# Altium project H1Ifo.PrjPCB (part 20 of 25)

## Sheet IfoEndY1.SchDoc: D1800185
size C; Engineer: Daniel Sigg; DocumentNumber: 5; Revision: 4; SheetNumber: 5; SheetTotal: 8
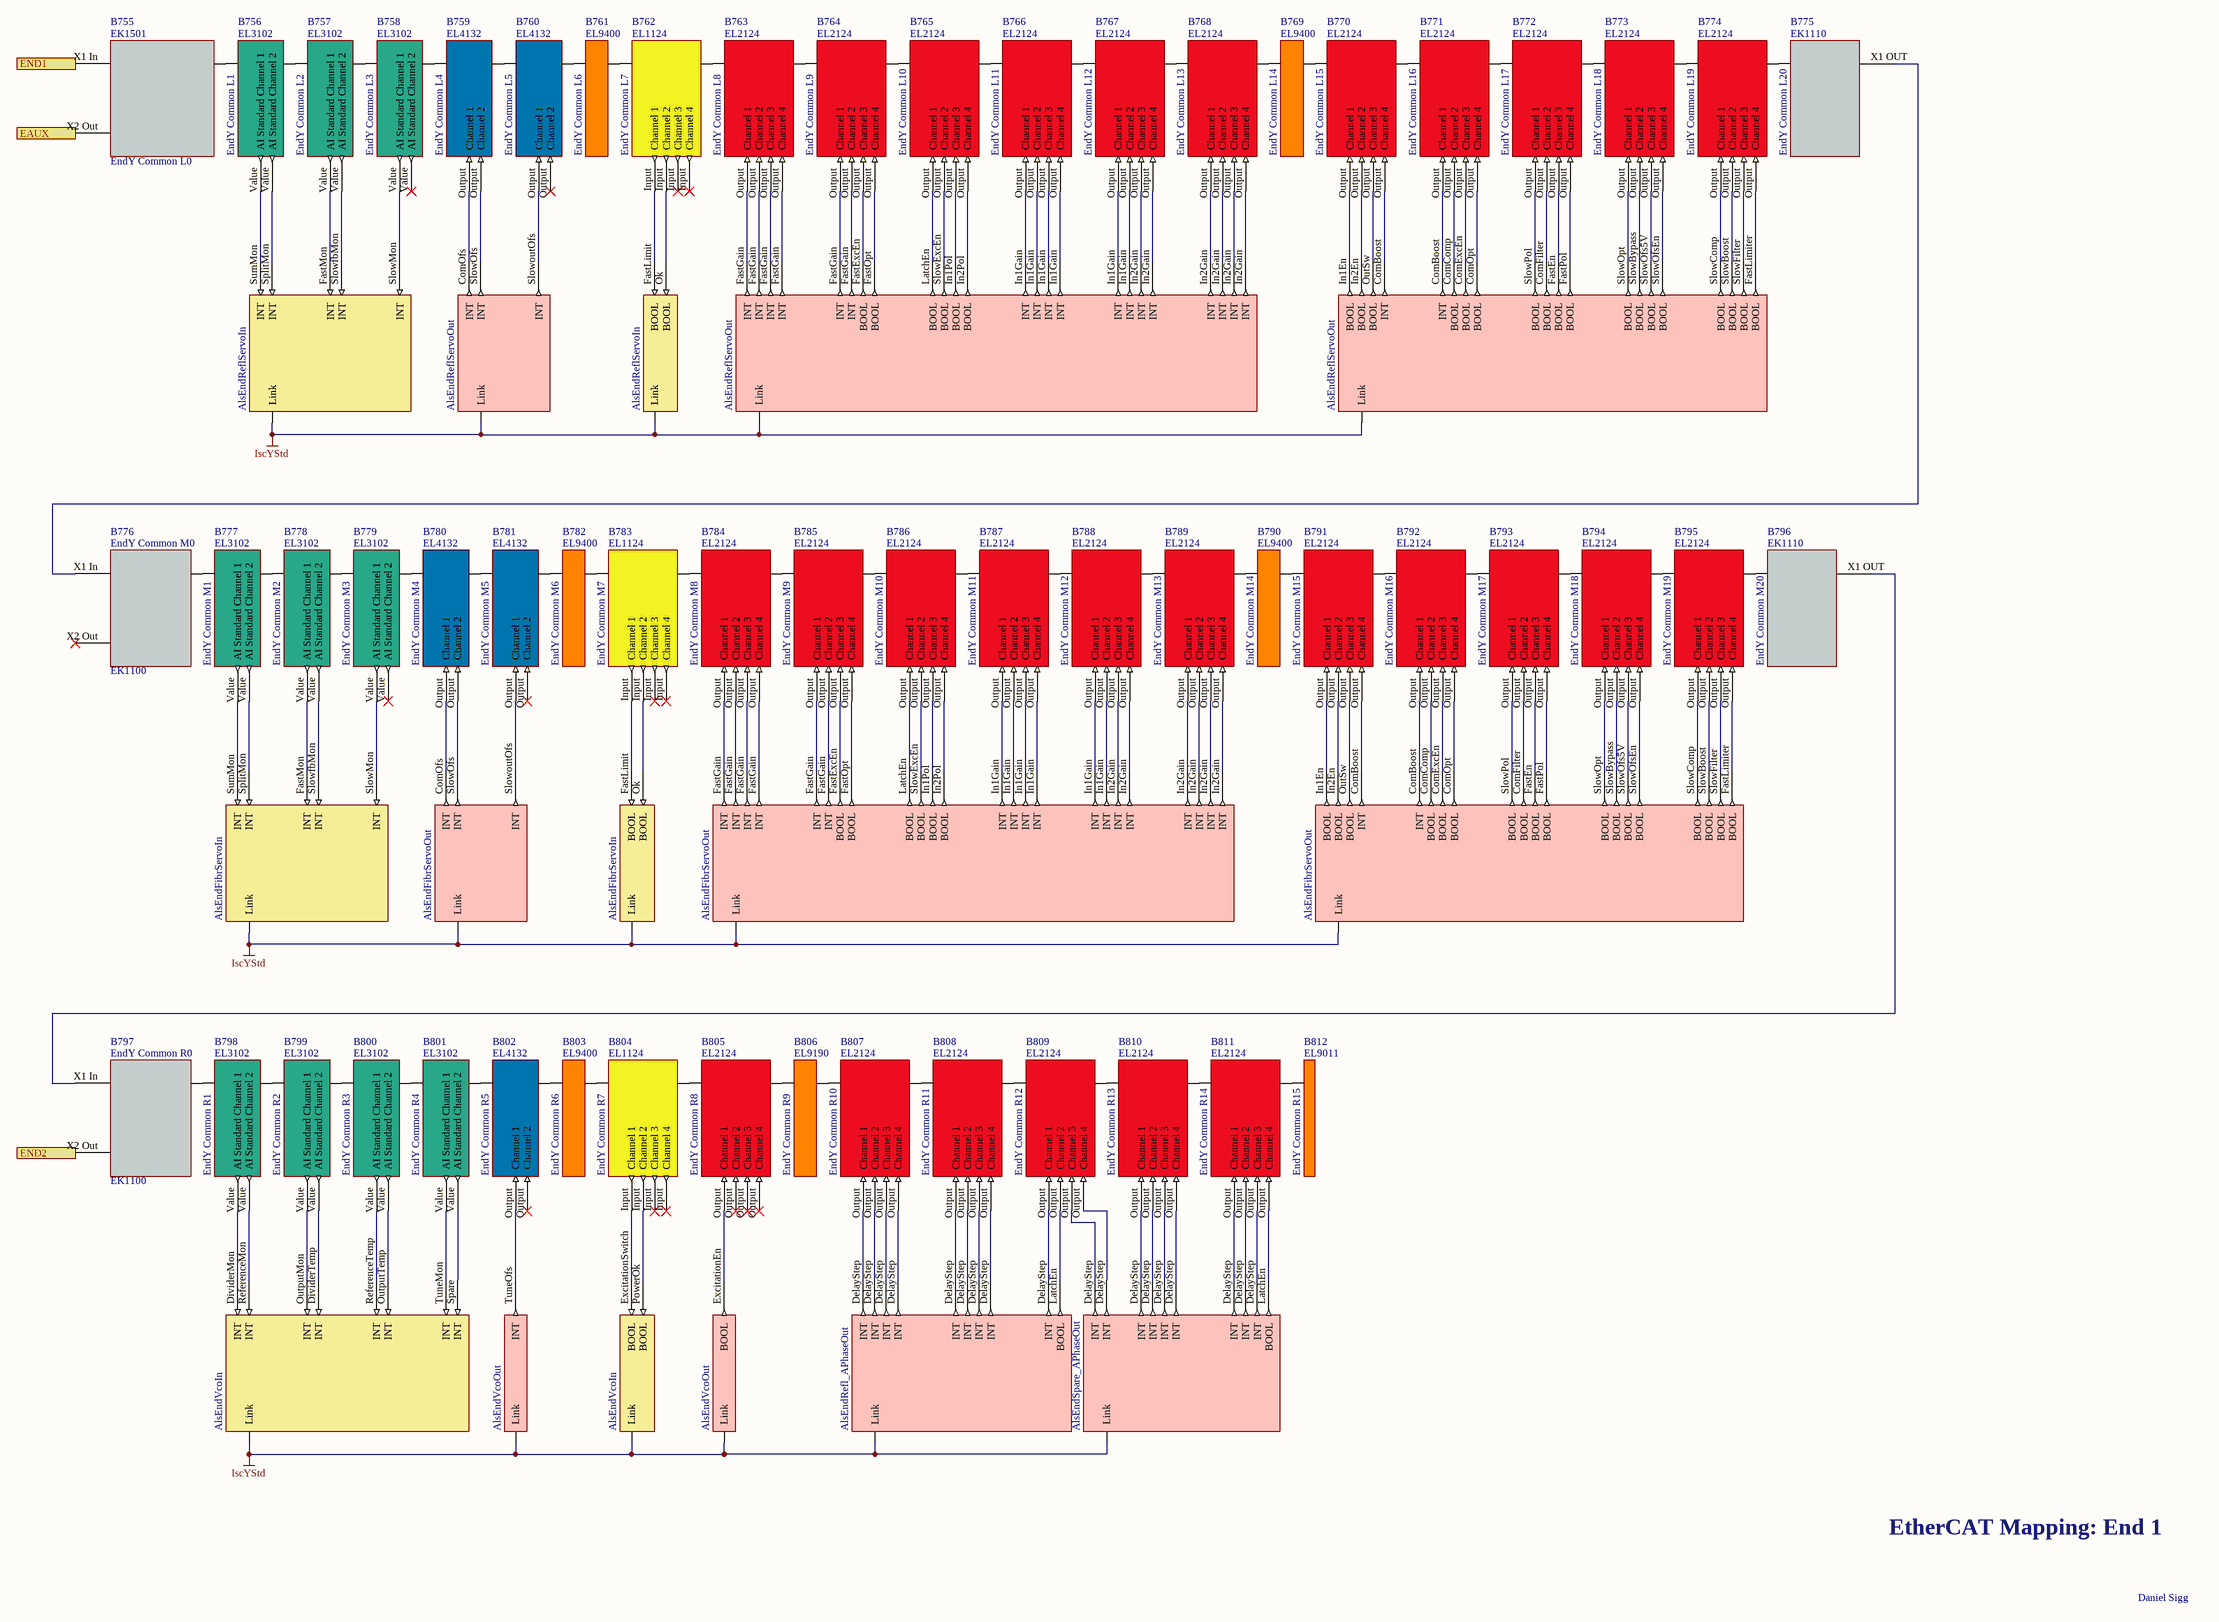
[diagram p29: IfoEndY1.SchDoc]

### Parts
B755  EndY Common L0  Part Number: EK1501  (mechanical)
B756  EndY Common L1  Part Number: EL3102  (mechanical)
B757  EndY Common L2  Part Number: EL3102  (mechanical)
B758  EndY Common L3  Part Number: EL3102  (mechanical)
B759  EndY Common L4  Part Number: EL4132  (mechanical)
B760  EndY Common L5  Part Number: EL4132  (mechanical)
B761  EndY Common L6  Part Number: EL9400  (mechanical)
B762  EndY Common L7  Part Number: EL1124  (mechanical)
B763  EndY Common L8  Part Number: EL2124  (mechanical)
B764  EndY Common L9  Part Number: EL2124  (mechanical)
B765  EndY Common L10  Part Number: EL2124  (mechanical)
B766  EndY Common L11  Part Number: EL2124  (mechanical)
B767  EndY Common L12  Part Number: EL2124  (mechanical)
B768  EndY Common L13  Part Number: EL2124  (mechanical)
B769  EndY Common L14  Part Number: EL9400  (mechanical)
B770  EndY Common L15  Part Number: EL2124  (mechanical)
B771  EndY Common L16  Part Number: EL2124  (mechanical)
B772  EndY Common L17  Part Number: EL2124  (mechanical)
B773  EndY Common L18  Part Number: EL2124  (mechanical)
B774  EndY Common L19  Part Number: EL2124  (mechanical)
B775  EndY Common L20  Part Number: EK1110  (mechanical)
B776  EndY Common M0  Part Number: EK1100  (mechanical)
B777  EndY Common M1  Part Number: EL3102  (mechanical)
B778  EndY Common M2  Part Number: EL3102  (mechanical)
B779  EndY Common M3  Part Number: EL3102  (mechanical)
B780  EndY Common M4  Part Number: EL4132  (mechanical)
B781  EndY Common M5  Part Number: EL4132  (mechanical)
B782  EndY Common M6  Part Number: EL9400  (mechanical)
B783  EndY Common M7  Part Number: EL1124  (mechanical)
B784  EndY Common M8  Part Number: EL2124  (mechanical)
B785  EndY Common M9  Part Number: EL2124  (mechanical)
B786  EndY Common M10  Part Number: EL2124  (mechanical)
B787  EndY Common M11  Part Number: EL2124  (mechanical)
B788  EndY Common M12  Part Number: EL2124  (mechanical)
B789  EndY Common M13  Part Number: EL2124  (mechanical)
B790  EndY Common M14  Part Number: EL9400  (mechanical)
B791  EndY Common M15  Part Number: EL2124  (mechanical)
B792  EndY Common M16  Part Number: EL2124  (mechanical)
B793  EndY Common M17  Part Number: EL2124  (mechanical)
B794  EndY Common M18  Part Number: EL2124  (mechanical)
B795  EndY Common M19  Part Number: EL2124  (mechanical)
B796  EndY Common M20  Part Number: EK1110  (mechanical)
B797  EndY Common R0  Part Number: EK1100  (mechanical)
B798  EndY Common R1  Part Number: EL3102  (mechanical)
B799  EndY Common R2  Part Number: EL3102  (mechanical)
B800  EndY Common R3  Part Number: EL3102  (mechanical)
B801  EndY Common R4  Part Number: EL3102  (mechanical)
B802  EndY Common R5  Part Number: EL4132  (mechanical)
B803  EndY Common R6  Part Number: EL9400  (mechanical)
B804  EndY Common R7  Part Number: EL1124  (mechanical)
B805  EndY Common R8  Part Number: EL2124  (mechanical)
B806  EndY Common R9  Part Number: EL9190  (mechanical)
B807  EndY Common R10  Part Number: EL2124  (mechanical)
B808  EndY Common R11  Part Number: EL2124  (mechanical)
B809  EndY Common R12  Part Number: EL2124  (mechanical)
B810  EndY Common R13  Part Number: EL2124  (mechanical)
B811  EndY Common R14  Part Number: EL2124  (mechanical)
B812  EndY Common R15  Part Number: EL9011  (mechanical)
V532  AlsEndVcoIn  (parts A,B of 2)  (no BOM)
V626  AlsEndReflServoIn  (parts A,B of 2)  (no BOM)
V627  AlsEndReflServoOut  (parts A,B,C of 3)  (no BOM)
V628  AlsEndFibrServoIn  (parts A,B of 2)  (no BOM)
V629  AlsEndFibrServoOut  (parts A,B,C of 3)  (no BOM)
V630  AlsEndVcoOut  (parts A,B of 2)  (no BOM)
V631  AlsEndRefl_APhaseOut  (no BOM)
V632  AlsEndSpare_APhaseOut  (no BOM)

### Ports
EAUX, END1, END2

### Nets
IscYStd: V532.0(Link) V532.1(Link) V626.1(Link) V626.?1(Link) V627.1(Link) V627.2(Link) V627.?1(Link) V628.1(Link) V628.?1(Link) V629.1(Link) V629.2(Link) V629.?1(Link) V630.0(Link) V630.1(Link) V631.?1(Link) V632.?1(Link)
NetB611_X1: B755.X1_In(A) ; port END1
NetB616_X2 Out: B755.X2_Out(C) ; port EAUX
NetB658_X2 Out: B797.X2_Out(C) ; port END2
NetB755_Ebus: B755.Ebus(B) B756.Ebus(A)
NetB756_Ebus: B756.Ebus(B) B757.Ebus(A)
NetB756_Value: B756.Value(AI_Standard_Channel_1) V626.SumMon(INT)
NetB756_Value: B756.Value(AI_Standard_Channel_2) V626.SplitMon(INT)  [a separate net that carries the same name]
NetB757_Ebus: B757.Ebus(B) B758.Ebus(A)
NetB757_Value: B757.Value(AI_Standard_Channel_1) V626.FastMon(INT)
NetB757_Value: B757.Value(AI_Standard_Channel_2) V626.SlowfbMon(INT)  [a separate net that carries the same name]
NetB758_Ebus: B758.Ebus(B) B759.Ebus(A)
NetB758_Value: B758.Value(AI_Standard_Channel_1) V626.SlowMon(INT)
NetB759_Ebus: B759.Ebus(B) B760.Ebus(A)
NetB759_Output: B759.Output(Channel_1) V627.ComOfs(INT)
NetB759_Output: B759.Output(Channel_2) V627.SlowOfs(INT)  [a separate net that carries the same name]
NetB760_Ebus: B760.Ebus(B) B761.Ebus(A)
NetB760_Output: B760.Output(Channel_1) V627.SlowoutOfs(INT)
NetB761_Ebus: B761.Ebus(B) B762.Ebus(A)
NetB762_Ebus: B762.Ebus(B) B763.Ebus(A)
NetB762_Input: B762.Input(Channel_1) V626.FastLimit(BOOL)
NetB762_Input: B762.Input(Channel_2) V626.Ok(BOOL)  [a separate net that carries the same name]
NetB763_Ebus: B763.Ebus(B) B764.Ebus(A)
NetB763_Output: B763.Output(Channel_1) V627.FastGain(INT)
NetB763_Output: B763.Output(Channel_2) V627.FastGain(INT)  [a separate net that carries the same name]
NetB763_Output: B763.Output(Channel_3) V627.FastGain(INT)  [a separate net that carries the same name]
NetB763_Output: B763.Output(Channel_4) V627.FastGain(INT)  [a separate net that carries the same name]
NetB764_Ebus: B764.Ebus(B) B765.Ebus(A)
NetB764_Output: B764.Output(Channel_1) V627.FastGain(INT)
NetB764_Output: B764.Output(Channel_2) V627.FastGain(INT)  [a separate net that carries the same name]
NetB764_Output: B764.Output(Channel_3) V627.FastExcEn(BOOL)  [a separate net that carries the same name]
NetB764_Output: B764.Output(Channel_4) V627.FastOpt(BOOL)  [a separate net that carries the same name]
NetB765_Ebus: B765.Ebus(B) B766.Ebus(A)
NetB765_Output: B765.Output(Channel_1) V627.LatchEn(BOOL)
NetB765_Output: B765.Output(Channel_2) V627.SlowExcEn(BOOL)  [a separate net that carries the same name]
NetB765_Output: B765.Output(Channel_3) V627.In1Pol(BOOL)  [a separate net that carries the same name]
NetB765_Output: B765.Output(Channel_4) V627.In2Pol(BOOL)  [a separate net that carries the same name]
NetB766_Ebus: B766.Ebus(B) B767.Ebus(A)
NetB766_Output: B766.Output(Channel_1) V627.In1Gain(INT)
NetB766_Output: B766.Output(Channel_2) V627.In1Gain(INT)  [a separate net that carries the same name]
NetB766_Output: B766.Output(Channel_3) V627.In1Gain(INT)  [a separate net that carries the same name]
NetB766_Output: B766.Output(Channel_4) V627.In1Gain(INT)  [a separate net that carries the same name]
NetB767_Ebus: B767.Ebus(B) B768.Ebus(A)
NetB767_Output: B767.Output(Channel_1) V627.In1Gain(INT)
NetB767_Output: B767.Output(Channel_2) V627.In1Gain(INT)  [a separate net that carries the same name]
NetB767_Output: B767.Output(Channel_3) V627.In2Gain(INT)  [a separate net that carries the same name]
NetB767_Output: B767.Output(Channel_4) V627.In2Gain(INT)  [a separate net that carries the same name]
NetB768_Ebus: B768.Ebus(B) B769.Ebus(A)
NetB768_Output: B768.Output(Channel_1) V627.In2Gain(INT)
NetB768_Output: B768.Output(Channel_2) V627.In2Gain(INT)  [a separate net that carries the same name]
NetB768_Output: B768.Output(Channel_3) V627.In2Gain(INT)  [a separate net that carries the same name]
NetB768_Output: B768.Output(Channel_4) V627.In2Gain(INT)  [a separate net that carries the same name]
NetB769_Ebus: B769.Ebus(B) B770.Ebus(A)
NetB770_Ebus: B770.Ebus(B) B771.Ebus(A)
NetB770_Output: B770.Output(Channel_1) V627.In1En(BOOL)
NetB770_Output: B770.Output(Channel_2) V627.In2En(BOOL)  [a separate net that carries the same name]
NetB770_Output: B770.Output(Channel_3) V627.OutSw(BOOL)  [a separate net that carries the same name]
NetB770_Output: B770.Output(Channel_4) V627.ComBoost(INT)  [a separate net that carries the same name]
NetB771_Ebus: B771.Ebus(B) B772.Ebus(A)
NetB771_Output: B771.Output(Channel_1) V627.ComBoost(INT)
NetB771_Output: B771.Output(Channel_2) V627.ComComp(BOOL)  [a separate net that carries the same name]
NetB771_Output: B771.Output(Channel_3) V627.ComExcEn(BOOL)  [a separate net that carries the same name]
NetB771_Output: B771.Output(Channel_4) V627.ComOpt(BOOL)  [a separate net that carries the same name]
NetB772_Ebus: B772.Ebus(B) B773.Ebus(A)
NetB772_Output: B772.Output(Channel_1) V627.SlowPol(BOOL)
NetB772_Output: B772.Output(Channel_2) V627.ComFilter(BOOL)  [a separate net that carries the same name]
NetB772_Output: B772.Output(Channel_3) V627.FastEn(BOOL)  [a separate net that carries the same name]
NetB772_Output: B772.Output(Channel_4) V627.FastPol(BOOL)  [a separate net that carries the same name]
NetB773_Ebus: B773.Ebus(B) B774.Ebus(A)
NetB773_Output: B773.Output(Channel_1) V627.SlowOpt(BOOL)
NetB773_Output: B773.Output(Channel_2) V627.SlowBypass(BOOL)  [a separate net that carries the same name]
NetB773_Output: B773.Output(Channel_3) V627.SlowOfs5V(BOOL)  [a separate net that carries the same name]
NetB773_Output: B773.Output(Channel_4) V627.SlowOfsEn(BOOL)  [a separate net that carries the same name]
NetB774_Ebus: B774.Ebus(B) B775.Ebus(A)
NetB774_Output: B774.Output(Channel_1) V627.SlowComp(BOOL)
NetB774_Output: B774.Output(Channel_2) V627.SlowBoost(BOOL)  [a separate net that carries the same name]
NetB774_Output: B774.Output(Channel_3) V627.SlowFilter(BOOL)  [a separate net that carries the same name]
NetB774_Output: B774.Output(Channel_4) V627.FastLimiter(BOOL)  [a separate net that carries the same name]
NetB775_X1 OUT: B775.X1_OUT(B) B776.X1_In(A)
NetB776_Ebus: B776.Ebus(B) B777.Ebus(A)
NetB777_Ebus: B777.Ebus(B) B778.Ebus(A)
NetB777_Value: B777.Value(AI_Standard_Channel_1) V628.SumMon(INT)
NetB777_Value: B777.Value(AI_Standard_Channel_2) V628.SplitMon(INT)  [a separate net that carries the same name]
NetB778_Ebus: B778.Ebus(B) B779.Ebus(A)
NetB778_Value: B778.Value(AI_Standard_Channel_1) V628.FastMon(INT)
NetB778_Value: B778.Value(AI_Standard_Channel_2) V628.SlowfbMon(INT)  [a separate net that carries the same name]
NetB779_Ebus: B779.Ebus(B) B780.Ebus(A)
NetB779_Value: B779.Value(AI_Standard_Channel_1) V628.SlowMon(INT)
NetB780_Ebus: B780.Ebus(B) B781.Ebus(A)
NetB780_Output: B780.Output(Channel_1) V629.ComOfs(INT)
NetB780_Output: B780.Output(Channel_2) V629.SlowOfs(INT)  [a separate net that carries the same name]
NetB781_Ebus: B781.Ebus(B) B782.Ebus(A)
NetB781_Output: B781.Output(Channel_1) V629.SlowoutOfs(INT)
NetB782_Ebus: B782.Ebus(B) B783.Ebus(A)
NetB783_Ebus: B783.Ebus(B) B784.Ebus(A)
NetB783_Input: B783.Input(Channel_1) V628.FastLimit(BOOL)
NetB783_Input: B783.Input(Channel_2) V628.Ok(BOOL)  [a separate net that carries the same name]
NetB784_Ebus: B784.Ebus(B) B785.Ebus(A)
NetB784_Output: B784.Output(Channel_1) V629.FastGain(INT)
NetB784_Output: B784.Output(Channel_2) V629.FastGain(INT)  [a separate net that carries the same name]
NetB784_Output: B784.Output(Channel_3) V629.FastGain(INT)  [a separate net that carries the same name]
NetB784_Output: B784.Output(Channel_4) V629.FastGain(INT)  [a separate net that carries the same name]
NetB785_Ebus: B785.Ebus(B) B786.Ebus(A)
NetB785_Output: B785.Output(Channel_1) V629.FastGain(INT)
NetB785_Output: B785.Output(Channel_2) V629.FastGain(INT)  [a separate net that carries the same name]
NetB785_Output: B785.Output(Channel_3) V629.FastExcEn(BOOL)  [a separate net that carries the same name]
NetB785_Output: B785.Output(Channel_4) V629.FastOpt(BOOL)  [a separate net that carries the same name]
NetB786_Ebus: B786.Ebus(B) B787.Ebus(A)
NetB786_Output: B786.Output(Channel_1) V629.LatchEn(BOOL)
NetB786_Output: B786.Output(Channel_2) V629.SlowExcEn(BOOL)  [a separate net that carries the same name]
NetB786_Output: B786.Output(Channel_3) V629.In1Pol(BOOL)  [a separate net that carries the same name]
NetB786_Output: B786.Output(Channel_4) V629.In2Pol(BOOL)  [a separate net that carries the same name]
NetB787_Ebus: B787.Ebus(B) B788.Ebus(A)
NetB787_Output: B787.Output(Channel_1) V629.In1Gain(INT)
NetB787_Output: B787.Output(Channel_2) V629.In1Gain(INT)  [a separate net that carries the same name]
NetB787_Output: B787.Output(Channel_3) V629.In1Gain(INT)  [a separate net that carries the same name]
NetB787_Output: B787.Output(Channel_4) V629.In1Gain(INT)  [a separate net that carries the same name]
NetB788_Ebus: B788.Ebus(B) B789.Ebus(A)
NetB788_Output: B788.Output(Channel_1) V629.In1Gain(INT)
NetB788_Output: B788.Output(Channel_2) V629.In1Gain(INT)  [a separate net that carries the same name]
NetB788_Output: B788.Output(Channel_3) V629.In2Gain(INT)  [a separate net that carries the same name]
NetB788_Output: B788.Output(Channel_4) V629.In2Gain(INT)  [a separate net that carries the same name]
NetB789_Ebus: B789.Ebus(B) B790.Ebus(A)
NetB789_Output: B789.Output(Channel_1) V629.In2Gain(INT)
NetB789_Output: B789.Output(Channel_2) V629.In2Gain(INT)  [a separate net that carries the same name]
NetB789_Output: B789.Output(Channel_3) V629.In2Gain(INT)  [a separate net that carries the same name]
NetB789_Output: B789.Output(Channel_4) V629.In2Gain(INT)  [a separate net that carries the same name]
NetB790_Ebus: B790.Ebus(B) B791.Ebus(A)
NetB791_Ebus: B791.Ebus(B) B792.Ebus(A)
NetB791_Output: B791.Output(Channel_1) V629.In1En(BOOL)
NetB791_Output: B791.Output(Channel_2) V629.In2En(BOOL)  [a separate net that carries the same name]
NetB791_Output: B791.Output(Channel_3) V629.OutSw(BOOL)  [a separate net that carries the same name]
NetB791_Output: B791.Output(Channel_4) V629.ComBoost(INT)  [a separate net that carries the same name]
NetB792_Ebus: B792.Ebus(B) B793.Ebus(A)
NetB792_Output: B792.Output(Channel_1) V629.ComBoost(INT)
NetB792_Output: B792.Output(Channel_2) V629.ComComp(BOOL)  [a separate net that carries the same name]
NetB792_Output: B792.Output(Channel_3) V629.ComExcEn(BOOL)  [a separate net that carries the same name]
NetB792_Output: B792.Output(Channel_4) V629.ComOpt(BOOL)  [a separate net that carries the same name]
NetB793_Ebus: B793.Ebus(B) B794.Ebus(A)
NetB793_Output: B793.Output(Channel_1) V629.SlowPol(BOOL)
NetB793_Output: B793.Output(Channel_2) V629.ComFilter(BOOL)  [a separate net that carries the same name]
NetB793_Output: B793.Output(Channel_3) V629.FastEn(BOOL)  [a separate net that carries the same name]
NetB793_Output: B793.Output(Channel_4) V629.FastPol(BOOL)  [a separate net that carries the same name]
NetB794_Ebus: B794.Ebus(B) B795.Ebus(A)
NetB794_Output: B794.Output(Channel_1) V629.SlowOpt(BOOL)
NetB794_Output: B794.Output(Channel_2) V629.SlowBypass(BOOL)  [a separate net that carries the same name]
NetB794_Output: B794.Output(Channel_3) V629.SlowOfs5V(BOOL)  [a separate net that carries the same name]
NetB794_Output: B794.Output(Channel_4) V629.SlowOfsEn(BOOL)  [a separate net that carries the same name]
NetB795_Ebus: B795.Ebus(B) B796.Ebus(A)
NetB795_Output: B795.Output(Channel_1) V629.SlowComp(BOOL)
NetB795_Output: B795.Output(Channel_2) V629.SlowBoost(BOOL)  [a separate net that carries the same name]
NetB795_Output: B795.Output(Channel_3) V629.SlowFilter(BOOL)  [a separate net that carries the same name]
NetB795_Output: B795.Output(Channel_4) V629.FastLimiter(BOOL)  [a separate net that carries the same name]
NetB796_X1 OUT: B796.X1_OUT(B) B797.X1_In(A)
NetB797_Ebus: B797.Ebus(B) B798.Ebus(A)
NetB798_Ebus: B798.Ebus(B) B799.Ebus(A)
NetB798_Value: B798.Value(AI_Standard_Channel_1) V532.DividerMon(INT)
NetB798_Value: B798.Value(AI_Standard_Channel_2) V532.ReferenceMon(INT)  [a separate net that carries the same name]
NetB799_Ebus: B799.Ebus(B) B800.Ebus(A)
NetB799_Value: B799.Value(AI_Standard_Channel_1) V532.OutputMon(INT)
NetB799_Value: B799.Value(AI_Standard_Channel_2) V532.DividerTemp(INT)  [a separate net that carries the same name]
NetB800_Ebus: B800.Ebus(B) B801.Ebus(A)
NetB800_Value: B800.Value(AI_Standard_Channel_1) V532.ReferenceTemp(INT)
NetB800_Value: B800.Value(AI_Standard_Channel_2) V532.OutputTemp(INT)  [a separate net that carries the same name]
NetB801_Ebus: B801.Ebus(B) B802.Ebus(A)
NetB801_Value: B801.Value(AI_Standard_Channel_1) V532.TuneMon(INT)
NetB801_Value: B801.Value(AI_Standard_Channel_2) V532.Spare(INT)  [a separate net that carries the same name]
NetB802_Ebus: B802.Ebus(B) B803.Ebus(A)
NetB802_Output: B802.Output(Channel_1) V630.TuneOfs(INT)
NetB803_Ebus: B803.Ebus(B) B804.Ebus(A)
NetB804_Ebus: B804.Ebus(B) B805.Ebus(A)
NetB804_Input: B804.Input(Channel_1) V532.ExcitationSwitch(BOOL)
NetB804_Input: B804.Input(Channel_2) V532.PowerOk(BOOL)  [a separate net that carries the same name]
NetB805_Ebus: B805.Ebus(B) B806.Ebus(A)
NetB805_Output: B805.Output(Channel_1) V630.ExcitationEn(BOOL)
NetB806_Ebus: B806.Ebus(B) B807.Ebus(A)
NetB807_Ebus: B807.Ebus(B) B808.Ebus(A)
NetB807_Output: B807.Output(Channel_1) V631.DelayStep(INT)
NetB807_Output: B807.Output(Channel_2) V631.DelayStep(INT)  [a separate net that carries the same name]
NetB807_Output: B807.Output(Channel_3) V631.DelayStep(INT)  [a separate net that carries the same name]
NetB807_Output: B807.Output(Channel_4) V631.DelayStep(INT)  [a separate net that carries the same name]
NetB808_Ebus: B808.Ebus(B) B809.Ebus(A)
NetB808_Output: B808.Output(Channel_1) V631.DelayStep(INT)
NetB808_Output: B808.Output(Channel_2) V631.DelayStep(INT)  [a separate net that carries the same name]
NetB808_Output: B808.Output(Channel_3) V631.DelayStep(INT)  [a separate net that carries the same name]
NetB808_Output: B808.Output(Channel_4) V631.DelayStep(INT)  [a separate net that carries the same name]
NetB809_Ebus: B809.Ebus(B) B810.Ebus(A)
NetB809_Output: B809.Output(Channel_1) V631.DelayStep(INT)
NetB809_Output: B809.Output(Channel_2) V631.LatchEn(BOOL)  [a separate net that carries the same name]
NetB809_Output: B809.Output(Channel_3) V632.DelayStep(INT)  [a separate net that carries the same name]
NetB809_Output: B809.Output(Channel_4) V632.DelayStep(INT)  [a separate net that carries the same name]
NetB810_Ebus: B810.Ebus(B) B811.Ebus(A)
NetB810_Output: B810.Output(Channel_1) V632.DelayStep(INT)
NetB810_Output: B810.Output(Channel_2) V632.DelayStep(INT)  [a separate net that carries the same name]
NetB810_Output: B810.Output(Channel_3) V632.DelayStep(INT)  [a separate net that carries the same name]
NetB810_Output: B810.Output(Channel_4) V632.DelayStep(INT)  [a separate net that carries the same name]
NetB811_Ebus: B811.Ebus(B) B812.Ebus(A)
NetB811_Output: B811.Output(Channel_1) V632.DelayStep(INT)
NetB811_Output: B811.Output(Channel_2) V632.DelayStep(INT)  [a separate net that carries the same name]
NetB811_Output: B811.Output(Channel_3) V632.DelayStep(INT)  [a separate net that carries the same name]
NetB811_Output: B811.Output(Channel_4) V632.LatchEn(BOOL)  [a separate net that carries the same name]

Not connected (* = marked no-connect by the designer): B776 X2 Out(C)*

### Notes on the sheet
- EtherCAT Mapping: End 1
- Daniel Sigg

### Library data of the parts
B755 = CouplerEK1501: Fiber Coupler; Rail: Left; BoxNextB: SJXIGBSP; BoxNextC: KUHNJRYY; BoxPrev: CKQXTAKS; PortPrevFull: 1006/D; PortPrevShort: D 'X1'; Fullname: TIID^End Y (EtherCAT)^EndY Link L0 (EK1501-0010)^EndY Link L6 (EK1521)^EndY Common L0 (EK1501); BoxPorts: Junction; BoxAddr: 1007; Disabled: False
B756 = TerminalEL3102: EtherCAT Terminal EL3102 2-chn Analog Input; Rail: Left; BoxNextB: RVQCNRGI; BoxPrev: NEQKDDQF; PortPrevFull: 1007/B; PortPrevShort: B; Fullname: TIID^End Y (EtherCAT)^EndY Link L0 (EK1501-0010)^EndY Link L6 (EK1521)^EndY Common L0 (EK1501)^EndY Common L1 (EL3102); BoxAddr: 1008; Disabled: False
B757 = TerminalEL3102: EtherCAT Terminal EL3102 2-chn Analog Input; Rail: Left; BoxNextB: LBCXENVO; BoxPrev: SJXIGBSP; PortPrevFull: 1008/B; PortPrevShort: B; Fullname: TIID^End Y (EtherCAT)^EndY Link L0 (EK1501-0010)^EndY Link L6 (EK1521)^EndY Common L0 (EK1501)^EndY Common L2 (EL3102); BoxAddr: 1009; Disabled: False
B758 = TerminalEL3102: EtherCAT Terminal EL3102 2-chn Analog Input; Rail: Left; BoxNextB: VIGIPNNS; BoxPrev: RVQCNRGI; PortPrevFull: 1009/B; PortPrevShort: B; Fullname: TIID^End Y (EtherCAT)^EndY Link L0 (EK1501-0010)^EndY Link L6 (EK1521)^EndY Common L0 (EK1501)^EndY Common L3 (EL3102); BoxAddr: 1010; Disabled: False
B759 = TerminalEL4132: EtherCAT Terminal EL4132 2-chn Analog Ouput; Rail: Left; BoxNextB: MXSIACMH; BoxPrev: LBCXENVO; PortPrevFull: 1010/B; PortPrevShort: B; Fullname: TIID^End Y (EtherCAT)^EndY Link L0 (EK1501-0010)^EndY Link L6 (EK1521)^EndY Common L0 (EK1501)^EndY Common L4 (EL4132); BoxAddr: 1011; Disabled: False
B760 = TerminalEL4132: EtherCAT Terminal EL4132 2-chn Analog Ouput; Rail: Left; BoxNextB: XYHSUYBA; BoxPrev: VIGIPNNS; PortPrevFull: 1011/B; PortPrevShort: B; Fullname: TIID^End Y (EtherCAT)^EndY Link L0 (EK1501-0010)^EndY Link L6 (EK1521)^EndY Common L0 (EK1501)^EndY Common L5 (EL4132); BoxAddr: 1012; Disabled: False
B761 = TerminalEL9400: EtherCAT Terminal EL9400 Power; BoxType: TerminalPassive; Rail: Left; BoxNextB: YKIOIMGE; BoxPrev: MXSIACMH; PortPrevShort: B; Fullname: TIID^End Y (EtherCAT)^EndY Link L0 (EK1501-0010)^EndY Link L6 (EK1521)^EndY Common L0 (EK1501)^EndY Common L6 (EL9400); Disabled: False
B762 = TerminalEL1124: EtherCAT Terminal EL1124 4-chn Digital Input; Rail: Left; BoxNextB: OHHNINHL; BoxPrev: XYHSUYBA; PortPrevFull: 1012/B; PortPrevShort: B; Fullname: TIID^End Y (EtherCAT)^EndY Link L0 (EK1501-0010)^EndY Link L6 (EK1521)^EndY Common L0 (EK1501)^EndY Common L7 (EL1124); BoxAddr: 1013; Disabled: False
B763 = TerminalEL2124: EtherCAT Terminal EL2124 4-chn Digital Ouput; Rail: Left; BoxNextB: WSOKDATR; BoxPrev: YKIOIMGE; PortPrevFull: 1013/B; PortPrevShort: B; Fullname: TIID^End Y (EtherCAT)^EndY Link L0 (EK1501-0010)^EndY Link L6 (EK1521)^EndY Common L0 (EK1501)^EndY Common L8 (EL2124); BoxAddr: 1014; Disabled: False
B764 = TerminalEL2124: EtherCAT Terminal EL2124 4-chn Digital Ouput; Rail: Left; BoxNextB: RIRSSSVT; BoxPrev: OHHNINHL; PortPrevFull: 1014/B; PortPrevShort: B; Fullname: TIID^End Y (EtherCAT)^EndY Link L0 (EK1501-0010)^EndY Link L6 (EK1521)^EndY Common L0 (EK1501)^EndY Common L9 (EL2124); BoxAddr: 1015; Disabled: False
B765 = TerminalEL2124: EtherCAT Terminal EL2124 4-chn Digital Ouput; Rail: Left; BoxNextB: AJTGRDXI; BoxPrev: WSOKDATR; PortPrevFull: 1015/B; PortPrevShort: B; Fullname: TIID^End Y (EtherCAT)^EndY Link L0 (EK1501-0010)^EndY Link L6 (EK1521)^EndY Common L0 (EK1501)^EndY Common L10 (EL2124); BoxAddr: 1016; Disabled: False
B766 = TerminalEL2124: EtherCAT Terminal EL2124 4-chn Digital Ouput; Rail: Left; BoxNextB: FFFVQHOE; BoxPrev: RIRSSSVT; PortPrevFull: 1016/B; PortPrevShort: B; Fullname: TIID^End Y (EtherCAT)^EndY Link L0 (EK1501-0010)^EndY Link L6 (EK1521)^EndY Common L0 (EK1501)^EndY Common L11 (EL2124); BoxAddr: 1017; Disabled: False
B767 = TerminalEL2124: EtherCAT Terminal EL2124 4-chn Digital Ouput; Rail: Left; BoxNextB: JQWBCRWP; BoxPrev: AJTGRDXI; PortPrevFull: 1017/B; PortPrevShort: B; Fullname: TIID^End Y (EtherCAT)^EndY Link L0 (EK1501-0010)^EndY Link L6 (EK1521)^EndY Common L0 (EK1501)^EndY Common L12 (EL2124); BoxAddr: 1018; Disabled: False
B768 = TerminalEL2124: EtherCAT Terminal EL2124 4-chn Digital Ouput; Rail: Left; BoxNextB: ULQBJNWH; BoxPrev: FFFVQHOE; PortPrevFull: 1018/B; PortPrevShort: B; Fullname: TIID^End Y (EtherCAT)^EndY Link L0 (EK1501-0010)^EndY Link L6 (EK1521)^EndY Common L0 (EK1501)^EndY Common L13 (EL2124); BoxAddr: 1019; Disabled: False
B769 = TerminalEL9400: EtherCAT Terminal EL9400 Power; BoxType: TerminalPassive; Rail: Left; BoxNextB: DAVJCMNS; BoxPrev: JQWBCRWP; PortPrevShort: B; Fullname: TIID^End Y (EtherCAT)^EndY Link L0 (EK1501-0010)^EndY Link L6 (EK1521)^EndY Common L0 (EK1501)^EndY Common L14 (EL9400); Disabled: False
B770 = TerminalEL2124: EtherCAT Terminal EL2124 4-chn Digital Ouput; Rail: Left; BoxNextB: LOMXSBTB; BoxPrev: ULQBJNWH; PortPrevFull: 1019/B; PortPrevShort: B; Fullname: TIID^End Y (EtherCAT)^EndY Link L0 (EK1501-0010)^EndY Link L6 (EK1521)^EndY Common L0 (EK1501)^EndY Common L15 (EL2124); BoxAddr: 1020; Disabled: False
B771 = TerminalEL2124: EtherCAT Terminal EL2124 4-chn Digital Ouput; Rail: Left; BoxNextB: BMPCRQJV; BoxPrev: DAVJCMNS; PortPrevFull: 1020/B; PortPrevShort: B; Fullname: TIID^End Y (EtherCAT)^EndY Link L0 (EK1501-0010)^EndY Link L6 (EK1521)^EndY Common L0 (EK1501)^EndY Common L16 (EL2124); BoxAddr: 1021; Disabled: False
B772 = TerminalEL2124: EtherCAT Terminal EL2124 4-chn Digital Ouput; Rail: Left; BoxNextB: FJUOOXEU; BoxPrev: LOMXSBTB; PortPrevFull: 1021/B; PortPrevShort: B; Fullname: TIID^End Y (EtherCAT)^EndY Link L0 (EK1501-0010)^EndY Link L6 (EK1521)^EndY Common L0 (EK1501)^EndY Common L17 (EL2124); BoxAddr: 1022; Disabled: False
B773 = TerminalEL2124: EtherCAT Terminal EL2124 4-chn Digital Ouput; Rail: Left; BoxNextB: LHKPVCWU; BoxPrev: BMPCRQJV; PortPrevFull: 1022/B; PortPrevShort: B; Fullname: TIID^End Y (EtherCAT)^EndY Link L0 (EK1501-0010)^EndY Link L6 (EK1521)^EndY Common L0 (EK1501)^EndY Common L18 (EL2124); BoxAddr: 1023; Disabled: False
B774 = TerminalEL2124: EtherCAT Terminal EL2124 4-chn Digital Ouput; Rail: Left; BoxNextB: YJNGPHYX; BoxPrev: FJUOOXEU; PortPrevFull: 1023/B; PortPrevShort: B; Fullname: TIID^End Y (EtherCAT)^EndY Link L0 (EK1501-0010)^EndY Link L6 (EK1521)^EndY Common L0 (EK1501)^EndY Common L19 (EL2124); BoxAddr: 1024; Disabled: False
B775 = CouplerEK1110: EtherCAT Coupler Extension; BoxType: Terminal; Rail: Left; BoxNextB: YFWVXBOK; BoxPrev: LHKPVCWU; PortPrevFull: 1024/B; PortPrevShort: B; Fullname: TIID^End Y (EtherCAT)^EndY Link L0 (EK1501-0010)^EndY Link L6 (EK1521)^EndY Common L0 (EK1501)^EndY Common L20 (EK1110); BoxAddr: 1025; Disabled: False
B776 = CouplerEK1100: EtherCAT Coupler; Rail: Middle; BoxNextB: PYYODAUF; BoxPrev: YJNGPHYX; PortPrevFull: 1025/B; PortPrevShort: B 'X1 OUT'; Fullname: TIID^End Y (EtherCAT)^EndY Link L0 (EK1501-0010)^EndY Link L6 (EK1521)^EndY Common M0 (EK1100); BoxPorts: Junction; BoxAddr: 1026; Disabled: False
B777 = TerminalEL3102: EtherCAT Terminal EL3102 2-chn Analog Input; Rail: Middle; BoxNextB: XJTTASJC; BoxPrev: YFWVXBOK; PortPrevFull: 1026/B; PortPrevShort: B; Fullname: TIID^End Y (EtherCAT)^EndY Link L0 (EK1501-0010)^EndY Link L6 (EK1521)^EndY Common M0 (EK1100)^EndY Common M1 (EL3102); BoxAddr: 1027; Disabled: False
B778 = TerminalEL3102: EtherCAT Terminal EL3102 2-chn Analog Input; Rail: Middle; BoxNextB: RCSWLFBG; BoxPrev: PYYODAUF; PortPrevFull: 1027/B; PortPrevShort: B; Fullname: TIID^End Y (EtherCAT)^EndY Link L0 (EK1501-0010)^EndY Link L6 (EK1521)^EndY Common M0 (EK1100)^EndY Common M2 (EL3102); BoxAddr: 1028; Disabled: False
B779 = TerminalEL3102: EtherCAT Terminal EL3102 2-chn Analog Input; Rail: Middle; BoxNextB: NUSADPYA; BoxPrev: XJTTASJC; PortPrevFull: 1028/B; PortPrevShort: B; Fullname: TIID^End Y (EtherCAT)^EndY Link L0 (EK1501-0010)^EndY Link L6 (EK1521)^EndY Common M0 (EK1100)^EndY Common M3 (EL3102); BoxAddr: 1029; Disabled: False
B780 = TerminalEL4132: EtherCAT Terminal EL4132 2-chn Analog Ouput; Rail: Middle; BoxNextB: GQVTVQEP; BoxPrev: RCSWLFBG; PortPrevFull: 1029/B; PortPrevShort: B; Fullname: TIID^End Y (EtherCAT)^EndY Link L0 (EK1501-0010)^EndY Link L6 (EK1521)^EndY Common M0 (EK1100)^EndY Common M4 (EL4132); BoxAddr: 1030; Disabled: False
B781 = TerminalEL4132: EtherCAT Terminal EL4132 2-chn Analog Ouput; Rail: Middle; BoxNextB: AFEBFTWL; BoxPrev: NUSADPYA; PortPrevFull: 1030/B; PortPrevShort: B; Fullname: TIID^End Y (EtherCAT)^EndY Link L0 (EK1501-0010)^EndY Link L6 (EK1521)^EndY Common M0 (EK1100)^EndY Common M5 (EL4132); BoxAddr: 1031; Disabled: False
B782 = TerminalEL9400: EtherCAT Terminal EL9400 Power; BoxType: TerminalPassive; Rail: Middle; BoxNextB: DHPLWSHO; BoxPrev: GQVTVQEP; PortPrevShort: B; Fullname: TIID^End Y (EtherCAT)^EndY Link L0 (EK1501-0010)^EndY Link L6 (EK1521)^EndY Common M0 (EK1100)^EndY Common M6 (EL9400); Disabled: False
B783 = TerminalEL1124: EtherCAT Terminal EL1124 4-chn Digital Input; Rail: Middle; BoxNextB: BQKCYRED; BoxPrev: AFEBFTWL; PortPrevFull: 1031/B; PortPrevShort: B; Fullname: TIID^End Y (EtherCAT)^EndY Link L0 (EK1501-0010)^EndY Link L6 (EK1521)^EndY Common M0 (EK1100)^EndY Common M7 (EL1124); BoxAddr: 1032; Disabled: False
B784 = TerminalEL2124: EtherCAT Terminal EL2124 4-chn Digital Ouput; Rail: Middle; BoxNextB: VYLHQYNV; BoxPrev: DHPLWSHO; PortPrevFull: 1032/B; PortPrevShort: B; Fullname: TIID^End Y (EtherCAT)^EndY Link L0 (EK1501-0010)^EndY Link L6 (EK1521)^EndY Common M0 (EK1100)^EndY Common M8 (EL2124); BoxAddr: 1033; Disabled: False
B785 = TerminalEL2124: EtherCAT Terminal EL2124 4-chn Digital Ouput; Rail: Middle; BoxNextB: PBOLLDTR; BoxPrev: BQKCYRED; PortPrevFull: 1033/B; PortPrevShort: B; Fullname: TIID^End Y (EtherCAT)^EndY Link L0 (EK1501-0010)^EndY Link L6 (EK1521)^EndY Common M0 (EK1100)^EndY Common M9 (EL2124); BoxAddr: 1034; Disabled: False
B786 = TerminalEL2124: EtherCAT Terminal EL2124 4-chn Digital Ouput; Rail: Middle; BoxNextB: PLHSIDAL; BoxPrev: VYLHQYNV; PortPrevFull: 1034/B; PortPrevShort: B; Fullname: TIID^End Y (EtherCAT)^EndY Link L0 (EK1501-0010)^EndY Link L6 (EK1521)^EndY Common M0 (EK1100)^EndY Common M10 (EL2124); BoxAddr: 1035; Disabled: False
B787 = TerminalEL2124: EtherCAT Terminal EL2124 4-chn Digital Ouput; Rail: Middle; BoxNextB: LWTHOLUO; BoxPrev: PBOLLDTR; PortPrevFull: 1035/B; PortPrevShort: B; Fullname: TIID^End Y (EtherCAT)^EndY Link L0 (EK1501-0010)^EndY Link L6 (EK1521)^EndY Common M0 (EK1100)^EndY Common M11 (EL2124); BoxAddr: 1036; Disabled: False
B788 = TerminalEL2124: EtherCAT Terminal EL2124 4-chn Digital Ouput; Rail: Middle; BoxNextB: SJMBTBEU; BoxPrev: PLHSIDAL; PortPrevFull: 1036/B; PortPrevShort: B; Fullname: TIID^End Y (EtherCAT)^EndY Link L0 (EK1501-0010)^EndY Link L6 (EK1521)^EndY Common M0 (EK1100)^EndY Common M12 (EL2124); BoxAddr: 1037; Disabled: False
B789 = TerminalEL2124: EtherCAT Terminal EL2124 4-chn Digital Ouput; Rail: Middle; BoxNextB: XKKUXAVC; BoxPrev: LWTHOLUO; PortPrevFull: 1037/B; PortPrevShort: B; Fullname: TIID^End Y (EtherCAT)^EndY Link L0 (EK1501-0010)^EndY Link L6 (EK1521)^EndY Common M0 (EK1100)^EndY Common M13 (EL2124); BoxAddr: 1038; Disabled: False
B790 = TerminalEL9400: EtherCAT Terminal EL9400 Power; BoxType: TerminalPassive; Rail: Middle; BoxNextB: OEJMIPWM; BoxPrev: SJMBTBEU; PortPrevShort: B; Fullname: TIID^End Y (EtherCAT)^EndY Link L0 (EK1501-0010)^EndY Link L6 (EK1521)^EndY Common M0 (EK1100)^EndY Common M14 (EL9400); Disabled: False
B791 = TerminalEL2124: EtherCAT Terminal EL2124 4-chn Digital Ouput; Rail: Middle; BoxNextB: RCDBIUUE; BoxPrev: XKKUXAVC; PortPrevFull: 1038/B; PortPrevShort: B; Fullname: TIID^End Y (EtherCAT)^EndY Link L0 (EK1501-0010)^EndY Link L6 (EK1521)^EndY Common M0 (EK1100)^EndY Common M15 (EL2124); BoxAddr: 1039; Disabled: False
B792 = TerminalEL2124: EtherCAT Terminal EL2124 4-chn Digital Ouput; Rail: Middle; BoxNextB: XCCCOPPI; BoxPrev: OEJMIPWM; PortPrevFull: 1039/B; PortPrevShort: B; Fullname: TIID^End Y (EtherCAT)^EndY Link L0 (EK1501-0010)^EndY Link L6 (EK1521)^EndY Common M0 (EK1100)^EndY Common M16 (EL2124); BoxAddr: 1040; Disabled: False
B793 = TerminalEL2124: EtherCAT Terminal EL2124 4-chn Digital Ouput; Rail: Middle; BoxNextB: IEEVPSNM; BoxPrev: RCDBIUUE; PortPrevFull: 1040/B; PortPrevShort: B; Fullname: TIID^End Y (EtherCAT)^EndY Link L0 (EK1501-0010)^EndY Link L6 (EK1521)^EndY Common M0 (EK1100)^EndY Common M17 (EL2124); BoxAddr: 1041; Disabled: False
B794 = TerminalEL2124: EtherCAT Terminal EL2124 4-chn Digital Ouput; Rail: Middle; BoxNextB: AWBRUXSI; BoxPrev: XCCCOPPI; PortPrevFull: 1041/B; PortPrevShort: B; Fullname: TIID^End Y (EtherCAT)^EndY Link L0 (EK1501-0010)^EndY Link L6 (EK1521)^EndY Common M0 (EK1100)^EndY Common M18 (EL2124); BoxAddr: 1042; Disabled: False
B795 = TerminalEL2124: EtherCAT Terminal EL2124 4-chn Digital Ouput; Rail: Middle; BoxNextB: YBORJYSG; BoxPrev: IEEVPSNM; PortPrevFull: 1042/B; PortPrevShort: B; Fullname: TIID^End Y (EtherCAT)^EndY Link L0 (EK1501-0010)^EndY Link L6 (EK1521)^EndY Common M0 (EK1100)^EndY Common M19 (EL2124); BoxAddr: 1043; Disabled: False
B796 = CouplerEK1110: EtherCAT Coupler Extension; BoxType: Terminal; Rail: Middle; BoxNextB: DRGVJRDF; BoxPrev: AWBRUXSI; PortPrevFull: 1043/B; PortPrevShort: B; Fullname: TIID^End Y (EtherCAT)^EndY Link L0 (EK1501-0010)^EndY Link L6 (EK1521)^EndY Common M0 (EK1100)^EndY Common M20 (EK1110); BoxAddr: 1044; Disabled: False
B797 = CouplerEK1100: EtherCAT Coupler; Rail: Right; BoxNextB: OYVQYNRP; BoxNextC: HQGQRHUW; BoxPrev: YBORJYSG; PortPrevFull: 1044/B; PortPrevShort: B 'X1 OUT'; Fullname: TIID^End Y (EtherCAT)^EndY Link L0 (EK1501-0010)^EndY Link L6 (EK1521)^EndY Common R0 (EK1100); BoxPorts: Junction; BoxAddr: 1045; Disabled: False
B798 = TerminalEL3102: EtherCAT Terminal EL3102 2-chn Analog Input; Rail: Right; BoxNextB: JBHEQFVQ; BoxPrev: DRGVJRDF; PortPrevFull: 1045/B; PortPrevShort: B; Fullname: TIID^End Y (EtherCAT)^EndY Link L0 (EK1501-0010)^EndY Link L6 (EK1521)^EndY Common R0 (EK1100)^EndY Common R1 (EL3102); BoxAddr: 1046; Disabled: False
B799 = TerminalEL3102: EtherCAT Terminal EL3102 2-chn Analog Input; Rail: Right; BoxNextB: AUWXWJXW; BoxPrev: OYVQYNRP; PortPrevFull: 1046/B; PortPrevShort: B; Fullname: TIID^End Y (EtherCAT)^EndY Link L0 (EK1501-0010)^EndY Link L6 (EK1521)^EndY Common R0 (EK1100)^EndY Common R2 (EL3102); BoxAddr: 1047; Disabled: False
B800 = TerminalEL3102: EtherCAT Terminal EL3102 2-chn Analog Input; Rail: Right; BoxNextB: VPAAUOLE; BoxPrev: JBHEQFVQ; PortPrevFull: 1047/B; PortPrevShort: B; Fullname: TIID^End Y (EtherCAT)^EndY Link L0 (EK1501-0010)^EndY Link L6 (EK1521)^EndY Common R0 (EK1100)^EndY Common R3 (EL3102); BoxAddr: 1048; Disabled: False
B801 = TerminalEL3102: EtherCAT Terminal EL3102 2-chn Analog Input; Rail: Right; BoxNextB: KQVWIMXB; BoxPrev: AUWXWJXW; PortPrevFull: 1048/B; PortPrevShort: B; Fullname: TIID^End Y (EtherCAT)^EndY Link L0 (EK1501-0010)^EndY Link L6 (EK1521)^EndY Common R0 (EK1100)^EndY Common R4 (EL3102); BoxAddr: 1049; Disabled: False
B802 = TerminalEL4132: EtherCAT Terminal EL4132 2-chn Analog Ouput; Rail: Right; BoxNextB: FRIHYYES; BoxPrev: VPAAUOLE; PortPrevFull: 1049/B; PortPrevShort: B; Fullname: TIID^End Y (EtherCAT)^EndY Link L0 (EK1501-0010)^EndY Link L6 (EK1521)^EndY Common R0 (EK1100)^EndY Common R5 (EL4132); BoxAddr: 1050; Disabled: False
B803 = TerminalEL9400: EtherCAT Terminal EL9400 Power; BoxType: TerminalPassive; Rail: Right; BoxNextB: RVQHAEVS; BoxPrev: KQVWIMXB; PortPrevShort: B; Fullname: TIID^End Y (EtherCAT)^EndY Link L0 (EK1501-0010)^EndY Link L6 (EK1521)^EndY Common R0 (EK1100)^EndY Common R6 (EL9400); Disabled: False
B804 = TerminalEL1124: EtherCAT Terminal EL1124 4-chn Digital Input; Rail: Right; BoxNextB: BATGKCCR; BoxPrev: FRIHYYES; PortPrevFull: 1050/B; PortPrevShort: B; Fullname: TIID^End Y (EtherCAT)^EndY Link L0 (EK1501-0010)^EndY Link L6 (EK1521)^EndY Common R0 (EK1100)^EndY Common R7 (EL1124); BoxAddr: 1051; Disabled: False
B805 = TerminalEL2124: EtherCAT Terminal EL2124 4-chn Digital Ouput; Rail: Right; BoxNextB: GANESNXI; BoxPrev: RVQHAEVS; PortPrevFull: 1051/B; PortPrevShort: B; Fullname: TIID^End Y (EtherCAT)^EndY Link L0 (EK1501-0010)^EndY Link L6 (EK1521)^EndY Common R0 (EK1100)^EndY Common R8 (EL2124); BoxAddr: 1052; Disabled: False
B806 = TerminalEL9190: EtherCAT Terminal EL9190 Supply; BoxType: TerminalPassive; Rail: Right; BoxNextB: TBTPBTKL; BoxPrev: BATGKCCR; PortPrevShort: B; Fullname: TIID^End Y (EtherCAT)^EndY Link L0 (EK1501-0010)^EndY Link L6 (EK1521)^EndY Common R0 (EK1100)^EndY Common R9 (EL9190); Disabled: False
B807 = TerminalEL2124: EtherCAT Terminal EL2124 4-chn Digital Ouput; Rail: Right; BoxNextB: KCDBYUOW; BoxPrev: GANESNXI; PortPrevFull: 1052/B; PortPrevShort: B; Fullname: TIID^End Y (EtherCAT)^EndY Link L0 (EK1501-0010)^EndY Link L6 (EK1521)^EndY Common R0 (EK1100)^EndY Common R10 (EL2124); BoxAddr: 1053; Disabled: False
B808 = TerminalEL2124: EtherCAT Terminal EL2124 4-chn Digital Ouput; Rail: Right; BoxNextB: HLTHLDLQ; BoxPrev: TBTPBTKL; PortPrevFull: 1053/B; PortPrevShort: B; Fullname: TIID^End Y (EtherCAT)^EndY Link L0 (EK1501-0010)^EndY Link L6 (EK1521)^EndY Common R0 (EK1100)^EndY Common R11 (EL2124); BoxAddr: 1054; Disabled: False
B809 = TerminalEL2124: EtherCAT Terminal EL2124 4-chn Digital Ouput; Rail: Right; BoxNextB: KCTPLAKD; BoxPrev: KCDBYUOW; PortPrevFull: 1054/B; PortPrevShort: B; Fullname: TIID^End Y (EtherCAT)^EndY Link L0 (EK1501-0010)^EndY Link L6 (EK1521)^EndY Common R0 (EK1100)^EndY Common R12 (EL2124); BoxAddr: 1055; Disabled: False
B810 = TerminalEL2124: EtherCAT Terminal EL2124 4-chn Digital Ouput; Rail: Right; BoxNextB: MNNLHIYC; BoxPrev: HLTHLDLQ; PortPrevFull: 1055/B; PortPrevShort: B; Fullname: TIID^End Y (EtherCAT)^EndY Link L0 (EK1501-0010)^EndY Link L6 (EK1521)^EndY Common R0 (EK1100)^EndY Common R13 (EL2124); BoxAddr: 1056; Disabled: False
B811 = TerminalEL2124: EtherCAT Terminal EL2124 4-chn Digital Ouput; Rail: Right; BoxNextB: YGRSYERH; BoxPrev: KCTPLAKD; PortPrevFull: 1056/B; PortPrevShort: B; Fullname: TIID^End Y (EtherCAT)^EndY Link L0 (EK1501-0010)^EndY Link L6 (EK1521)^EndY Common R0 (EK1100)^EndY Common R14 (EL2124); BoxAddr: 1057; Disabled: False
B812 = TerminalEL9011: EtherCAT Terminal EL9011 End; BoxType: TerminalPassive; Rail: Right; BoxPrev: MNNLHIYC; PortPrevShort: B; Fullname: TIID^End Y (EtherCAT)^EndY Link L0 (EK1501-0010)^EndY Link L6 (EK1521)^EndY Common R0 (EK1100)^EndY Common R15 (EL9011); Disabled: False
V532 = LowNoiseVco_LowNoiseVcoInStruct: LowNoiseVcoInStruct; BoxType: Variable; Instance: H1IscEndY Instance; PLC: H1IscEndY; Task: IscEStd
V626 V628 = CommonMode_CommonModeInStruct: CommonModeInStruct; BoxType: Variable; Instance: H1IscEndY Instance; PLC: H1IscEndY; Task: IscEStd
V627 V629 = CommonMode_CommonModeOutStruct: CommonModeOutStruct; BoxType: Variable; Instance: H1IscEndY Instance; PLC: H1IscEndY; Task: IscEStd
V630 = LowNoiseVco_LowNoiseVcoOutStruct: LowNoiseVcoOutStruct; BoxType: Variable; Instance: H1IscEndY Instance; PLC: H1IscEndY; Task: IscEStd
V631 = DelayLogic_DelayLogicOutStruct: DelayLogicOutStruct; BoxType: Variable; Instance: H1IscEndY Instance; PLC: H1IscEndY; Task: IscEStd
V632 = DelayLogic_DelayLogicOutStructB: DelayLogicOutStruct; BoxType: Variable; Instance: H1IscEndY Instance; PLC: H1IscEndY; Task: IscEStd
